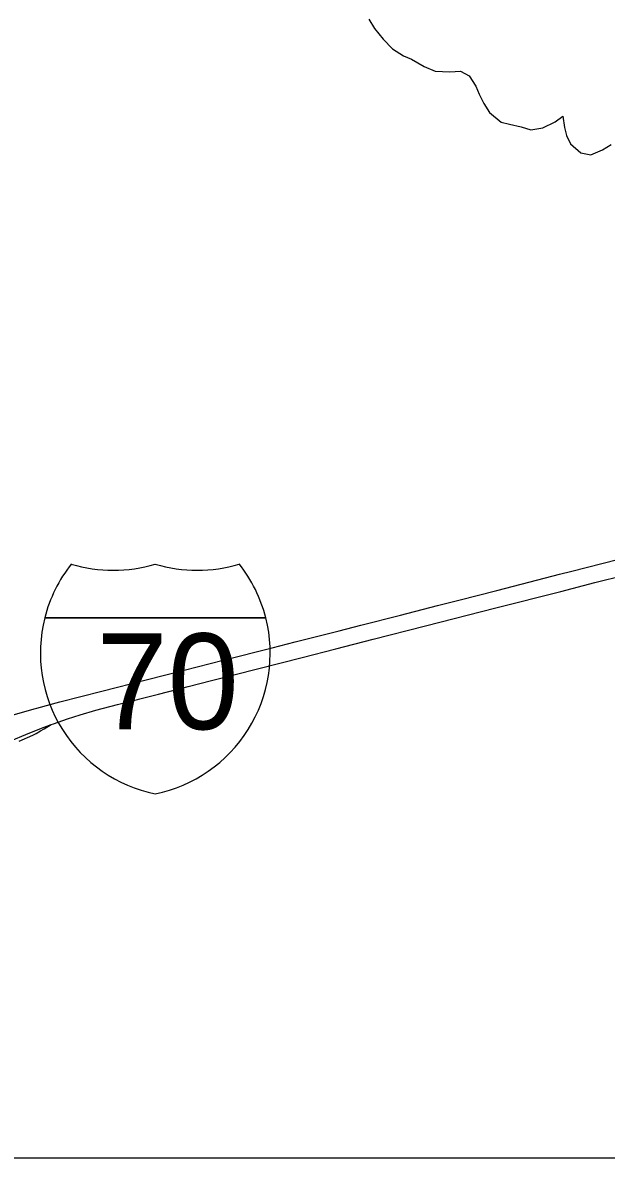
# Model space of a CAD drawing. Extents: x -29.6 to 34, y 0 to 22.
# Drawn here: x 6.177 to 7.023, y 13.504 to 15.149 of the extents above; entities that cross this region are included whole.
import ezdxf

# ---------------------------------------------------------------- set-up
doc = ezdxf.new("R2010")
doc.units = 0
for name, color, linetype in [('GM_X_Interchange_Ramps', 7, 'Continuous'), ('GM_X_Interstate_Route', 7, 'Continuous'), ('GM_X_Interstate_Shield', 7, 'Continuous'), ('GM_X_Minor_River', 7, 'Continuous'), ('SH_Text', 7, 'Continuous')]:
    doc.layers.add(name, color=color, linetype=linetype)

msp = doc.modelspace()

# ---------------------------------------------------------------- linework, layer by layer
at = {"layer": 'GM_X_Interchange_Ramps'}
msp.add_lwpolyline([(6.1722, 14.1081), (6.1922, 14.117), (6.1969, 14.1194), (6.2033, 14.123), (6.2088, 14.1263), (6.2149, 14.13), (6.2188, 14.1323)], dxfattribs=at)
at = {"layer": 'GM_X_Interstate_Route'}
for points in [[(6.1943, 14.1552), (6.1978, 14.1562), (6.2315, 14.1653), (6.2922, 14.1807), (6.3563, 14.1972), (6.4114, 14.2112), (6.4678, 14.2255), (6.5391, 14.2436), (6.5723, 14.2521), (6.6358, 14.2682), (6.6675, 14.2763), (6.7247, 14.2909), (6.7782, 14.3047), (6.8093, 14.3126), (6.8643, 14.3265), (6.9348, 14.3446), (6.9553, 14.3499), (6.9729, 14.3544), (7.0392, 14.3713)], [(6.4173, 14.1873), (6.4512, 14.196), (6.5175, 14.213), (6.5824, 14.2296), (6.6311, 14.242), (6.6854, 14.256), (6.7608, 14.2753), (6.8631, 14.3012), (6.9569, 14.3252), (7.0063, 14.3378), (7.0493, 14.3488)], [(6.2188, 14.1323), (6.2222, 14.1335), (6.2422, 14.1404), (6.2609, 14.1464), (6.2833, 14.1529), (6.315, 14.1613), (6.3743, 14.1763), (6.4173, 14.1873)], [(6.1145, 14.1314), (6.1252, 14.1347), (6.1405, 14.1394), (6.1656, 14.147), (6.1943, 14.1552)], [(5.9898, 14.0074), (5.9986, 14.0141), (6.0164, 14.0269), (6.0326, 14.038), (6.0516, 14.0503), (6.0702, 14.0617), (6.0885, 14.0724), (6.1038, 14.0808), (6.1219, 14.0902), (6.1422, 14.1002), (6.1613, 14.1091), (6.1821, 14.118), (6.2024, 14.1261), (6.2188, 14.1323)]]:
    msp.add_lwpolyline(points, dxfattribs=at)
at = {"layer": 'GM_X_Interstate_Shield'}
for p, q in [((6.2094, 14.2868), (6.5297, 14.2868)), ((6.5297, 14.2868), (6.2094, 14.2868)), ((6.5297, 14.2868), (6.2094, 14.2868))]:
    msp.add_line(p, q, dxfattribs=at)
for centre, start, end in [((6.4112, 14.2358), 141.669, 165.8066), ((6.3087, 14.5638), 253.0091, 286.9909), ((6.4304, 14.5638), 253.0091, 286.9909), ((6.3279, 14.2358), 14.1934, 38.331), ((6.4112, 14.2358), 165.8066, 258.463), ((6.3279, 14.2358), 281.537, 14.1934)]:
    msp.add_arc(centre, 0.2081, start, end, dxfattribs=at)
at = {"layer": 'GM_X_Minor_River'}
for points in [[(6.6788, 15.1537), (6.6873, 15.1405), (6.6998, 15.125), (6.7132, 15.1109), (6.7292, 15.1008), (6.7407, 15.096), (6.759, 15.0855), (6.7749, 15.0785), (6.7962, 15.0777), (6.8117, 15.0787), (6.8242, 15.0717), (6.834, 15.0567)], [(6.834, 15.0567), (6.8389, 15.0452), (6.8457, 15.0319), (6.8537, 15.0187), (6.8707, 15.0046), (6.8826, 15.002), (6.8995, 14.9981), (6.9137, 14.9938), (6.931, 14.9966), (6.9486, 15.0051), (6.9601, 15.0132), (6.9624, 14.9972), (6.9651, 14.9853), (6.971, 14.9733), (6.9861, 14.9601), (7.0003, 14.9575), (7.0175, 14.9648), (7.0299, 14.9724)]]:
    msp.add_lwpolyline(points, dxfattribs=at)
at = {"layer": 'SH_Text'}
msp.add_line((20.8747, 13.5041), (2.5893, 13.5041), dxfattribs=at)

# ---------------------------------------------------------------- texts
at = {"layer": 'GM_X_Interstate_Shield'}
msp.add_text('70', height=0.13872, dxfattribs=at).set_placement((6.2843, 14.1255))

doc.saveas('drawing.dxf')
